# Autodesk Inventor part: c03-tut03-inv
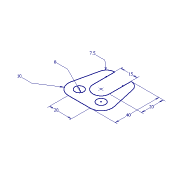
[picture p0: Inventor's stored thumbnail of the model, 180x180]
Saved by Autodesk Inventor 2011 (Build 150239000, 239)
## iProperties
Created: 2010-01
Part Number: c03-tut03-inv
Document SubType Name: Modeling
Designer: CADSoft
Density: 1 g/cm^3
Author: CADSoft
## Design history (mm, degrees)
sketch "Sketch1"
  geometry: L1 (-10, -20)-(10, -20); L2 (19.756, -7.805)-(14.817, 14.146); L3 (7.5, 20)-(7.5, 0); L4 (-7.5, 0)-(-7.5, 20); L5 (-14.817, 14.146)-(-19.756, -7.805); C1 r 4 at (-10, -10); C2 r 4 at (10, -10); A1 r 10 centre (10, -10) between (10, -20) and (19.756, -7.805); A2 r 7.5 centre (7.5, 12.5) between (14.817, 14.146) and (7.5, 20); A3 r 7.5 centre (0, 0) between (-7.5, 0) and (7.5, 0); A4 r 7.5 centre (-7.5, 12.5) between (-7.5, 20) and (-14.817, 14.146); A5 r 10 centre (-10, -10) between (-19.756, -7.805) and (-10, -20); 2 further points
  constraints: 10 end point, 10 point on circle, 8 tangent, 7 centre point, 4 coincident, 3 equal radius, 2 equal length, 2 point on line, 2 vertical, 1 horizontal, 1 other
  dimensions: "d0" = 20 distance of L1.start L1.end; "d1" = 7.5 radius of A4; "d2" = 10 radius of A5; "d3" = 15 distance between parallel lines of L3 L4; "d4" = 20 distance of L3.start L3.end; "d5" = 40 distance from line of L1 L3.start; "d6" = 8 diameter of C1
